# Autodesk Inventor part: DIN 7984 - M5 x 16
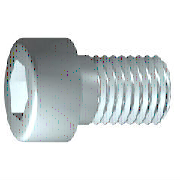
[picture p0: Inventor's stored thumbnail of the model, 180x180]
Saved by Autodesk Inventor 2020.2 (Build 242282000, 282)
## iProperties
Manager: www.cadconsulting.pl
Company: Fabian Stasiak CAD Consulting
Created: 2011-02
Part Number: DIN 7984 - M5 x 16
Material: Stal, miękka
Description: Wkręt z łbem półkolistym walcowym
Document SubType Name: Modeling
Standard: DIN 7984
Designer: F.Stasiak
Standard Revision: 1985
Standards Organization: DIN
Language: pl-PL
Size Designation: M5 x 16
Categories: <MemberInstance><Categories><Category DisplayName="Mocowania" InternalName="e4da775c-781d-43d5-af7c-5136215cf5a6" Mnemonic="FSTN"><Category DisplayName="Śruby"
Density: 1 g/cm^3
Appearance: Metal-Stal
IsCustomPart: 0
Author: F.Stasiak
Subject: Zbiór ćwiczeń. Autodesk Inventor 2020. Kurs podstawowy
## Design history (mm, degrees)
sketch "Szkic1"
  geometry: L1 (0.2, 0)-(16, 0); L2 (16, 0)-(16, 2.5); L3 (16, 2.5)-(2.4, 2.5); L4 (2.4, 2.5)-(1.909, 2.5); L5 (1.909, 2.5)-(0, 2.5); L6 (0, 2.5)-(0, 4.25); L7 (0, 4.25)-(-3.5, 4.25); L8 (-3.5, 4.25)-(-3.5, 1.732); L9 (-3.5, 1.732)-(-0.8, 1.732); L10 (-0.8, 1.732)-(0.2, 0); L11 (-7.4, 0)-(19.9, 0) reference; L12 (0, -0.85)-(0, 5.1) reference; L13 (2.4, 2.5)-(0, 2.5)
  constraints: 22 end point, 6 parallel, 2 collinear, 2 perpendicular, 1 horizontal, 1 point on line
  dimensions: "d1" = 13.6 distance from line of L3.end L2 (= GEL); "d2" = 0.49086 distance of L4.end L3.end (computed from GAL); "d3" = 3.5 distance between parallel lines of L8 L6 (= KOH); "d4" = 2.7 distance of L8.end L9.end (= INTI); "d5" = 60 deg angle of L10 L1; "d6" = 5 diameter of L3 L1 (= GD); "d7" = 5 diameter of L5 L1 (= BDM); "d8" = 3.4641 diameter of L9 L1 (= 1.1547 x SW); "d9" = 8.5 diameter of L7 L1 (= KOD); "d26" = 16 distance between parallel lines of L12 L2 (= NLG)
revolve "Bryła" sketch "Szkic1" stored, may be unused: angle "d10" = 90 deg
sketch "Szkic2"
  geometry: L1 (0, -5.95)-(0, 5.95) reference; L2 (-5.95, 0)-(5.95, 0) reference; L3 (1.732, 0)-(0.866, -1.5); L4 (0.866, -1.5)-(-0.866, -1.5); L5 (-0.866, -1.5)-(-1.732, 0); L6 (-1.732, 0)-(-0.866, 1.5); L7 (-0.866, 1.5)-(0.866, 1.5); L8 (0.866, 1.5)-(1.732, 0); 2 further points
  constraints: 12 end point, 1 coincident, 1 horizontal alignment, 1 point on line, 12 other
extrude "Szczelina" join sketch "Szkic2" stored distance "d11" = 10; taper "d12" = 0 deg
workplane "Work Plane1"
fillet "Fillet2" dims "d30" = 0.1 (= R)
body "Solid1"
fillet "Zaokrąglenie1" dims "d17" = 0.5 (= RR)
feature "Gwint" dims "d13" = 13.6 (= GEL), "d14" = 0
chamfer "Faza1" distance "d15" = 0.49076 (= -0.5 x SPD + 0.5 x GD); stored, may be unused: second distance "d16" = 0.49076 (= GUL), angle "d27" = 45 deg
other parameters: "GD" = 5 (= NND) [user parameter; used in 2 equation terms], "NLG" = 16 [user parameter; used in 1 equation term], "GEL" = 13.6 [user parameter; used in 2 equation terms], "KOD" = 8.5 [user parameter; used in 1 equation term], "KOH" = 3.5 [user parameter; used in 1 equation term], "INTI" = 2.7 [user parameter; used in 1 equation term], "GAL" = 0.49076 (= 0.61345 x PTC) [user parameter; used in 1 equation term], "GUL" = 0.49076 (= 0.61345 x PTC) [user parameter; used in 1 equation term], "BDM" = 5 (= NND) [user parameter; used in 1 equation term], "SW" = 3 [user parameter; used in 2 equation terms], "RR" = 0.5 [user parameter; used in 1 equation term], "SPD" = 4.01848 (= NND - 1.2269 x PTC) [user parameter; used in 1 equation term], "d19" = 0, "d28" = 0, "d29" = 0, "R" = 0.1 [user parameter; used in 1 equation term], "TOA" = 30 deg [user parameter], "GD1" = 4.01848 (= THREADDIA - 1.2269 x PTC) [user parameter], "THREADDIA" = 5 [user parameter; used in 1 equation term], "FAWI" = 45 deg [user parameter], "ANG" = 120 deg [user parameter], "TPU" = 12.5 (computed from PTC) [user parameter], "PTC" = 0.8 [user parameter; used in 5 equation terms], "NND" = 5 [user parameter; used in 3 equation terms], "E0" = 3.465 (= 1.155 x SW) [user parameter]
